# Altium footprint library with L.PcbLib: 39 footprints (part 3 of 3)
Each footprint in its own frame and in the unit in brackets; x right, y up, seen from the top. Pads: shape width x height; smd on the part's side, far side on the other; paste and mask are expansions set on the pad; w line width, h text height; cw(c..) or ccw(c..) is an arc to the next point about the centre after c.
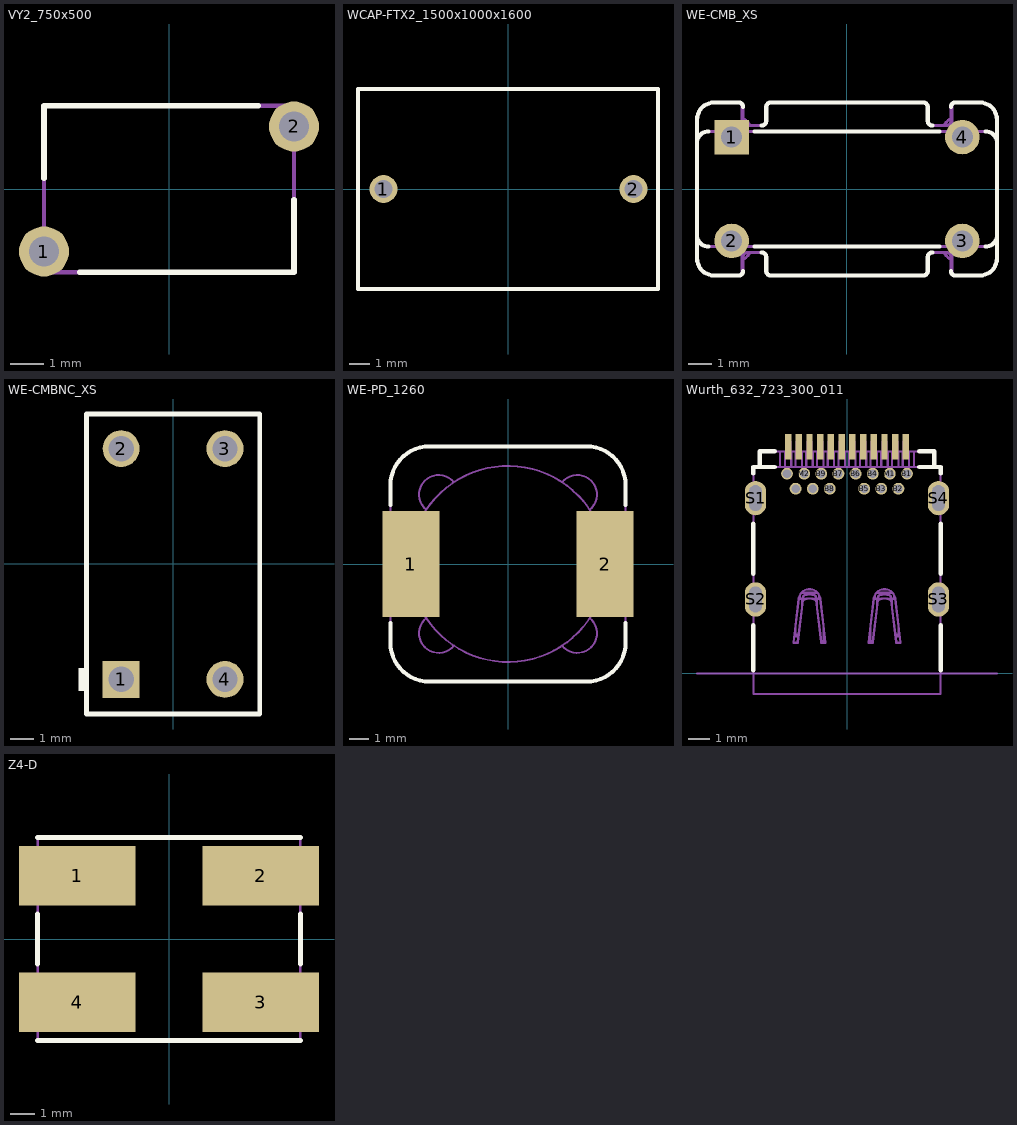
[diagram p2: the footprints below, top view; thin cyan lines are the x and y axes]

## VY2_750x500 [mm] "Vishay"
height 10.5
pads (2):
  round 1.5 hole 0.889: 1(-3.75,-1.875) 2(3.75,1.875)
Top Overlay:
  lines w0.17: -3.75,0.325 -3.75,2.5 2.675,2.5 ; -2.675,-2.5 3.75,-2.5 3.75,-0.325
Mechanical 5:
  lines w0.127: -3.75,-1.25 -3.75,1.25 ; 3.75,-1.25 3.75,1.25 ; -3.75,-2.5 -3.75,2.5 3.75,2.5 3.75,-2.5 -3.75,-2.5
3D body: height 5.5, standoff -1.5, extent -4.05,-2.174 -3.452,-1.576
3D body: height 5.5, standoff -1.5, extent 3.45,1.576 4.048,2.174
3D body: height 10.5, standoff 3, extent -3.75,-2.5 3.75,2.5

## WCAP-FTX2_1500x1000x1600 [mm] "TH, 2-Leads, Body 15x10mm, Pin Spacing 12.5mm"
height 16.5
pads (2):
  round 1.4 hole 0.9: 1(-6.25,0) 2(6.25,0)
Top Overlay:
  lines w0.2: -7.525,-5 7.475,-5 7.475,5 -7.525,5 -7.525,-5
Mechanical 5:
  lines w0.1: -7.525,-5 -7.525,5 7.475,5 7.475,-5 -7.525,-5
3D body "890324024005.stp": height 16, standoff -20, extent -7.5,-5 7.5,5

## WE-CMB_XS [mm] "WE-CMB Series Size XS"
height 18
pads (4):
  rect 1.5x1.5 hole 0.9: 1(-5,2.25)
  round 1.5 hole 0.9: 2(-5,-2.25) 3(5,-2.25) 4(5,2.25)
Top Overlay:
  lines w0.178: -6,-2.5 cw(c-6,-2) -6.5,-2 ; -6,2.5 ccw(c-6,2) -6.5,2 ; -4.5,-3.55 cw(c-4.7,-3.55) -4.543,-3.674 cw(c-4.7,-3.55) -4.7,-3.75 -5.75,-3.75 cw(c-5.75,-3) -6.5,-3 -6.5,-2 ; -4.5,3.55 ccw(c-4.7,3.55) -4.543,3.674 ccw(c-4.7,3.55) -4.7,3.75 -5.75,3.75 ccw(c-5.75,3) -6.5,3 -6.5,2 ; -4,-2.5 0,-2.5 4,-2.5 ; -4,2.5 0,2.5 4,2.5 ; -3.7,-2.75 cw(c-3.7,-2.95) -3.5,-2.95 -3.5,-3.55 ccw(c-3.3,-3.55) -3.3,-3.75 3.3,-3.75 ccw(c3.3,-3.55) 3.5,-3.55 3.5,-2.95 cw(c3.7,-2.95) 3.7,-2.75 ; -3.7,2.75 ccw(c-3.7,2.95) -3.5,2.95 -3.5,3.55 cw(c-3.3,3.55) -3.3,3.75 3.3,3.75 cw(c3.3,3.55) 3.5,3.55 3.5,2.95 ccw(c3.7,2.95) 3.7,2.75 ; 4.5,-3.55 ccw(c4.7,-3.55) 4.543,-3.674 ccw(c4.7,-3.55) 4.7,-3.75 5.75,-3.75 ccw(c5.75,-3) 6.5,-3 6.5,-2 ; 4.5,3.55 cw(c4.7,3.55) 4.543,3.674 cw(c4.7,3.55) 4.7,3.75 5.75,3.75 cw(c5.75,3) 6.5,3 6.5,2 ; 6,-2.5 ccw(c6,-2) 6.5,-2 ; 6,2.5 cw(c6,2) 6.5,2 ; -6.5,-2 -6.5,2 ; 6.5,-2 6.5,2
Mechanical 5:
  lines w0.127: -4.543,-2.5 -4.543,-3.674 ; -4.543,2.5 -4.543,3.674 ; -4.5,-3.058 ccw(c-5,-2.25) -4.192,-2.75 ; -4.5,3.058 cw(c-5,2.25) -4.192,2.75 ; 4.192,-2.75 ccw(c5,-2.25) 4.5,-3.058 ; 4.192,2.75 cw(c5,2.25) 4.5,3.058 ; 4.543,-2.5 4.543,-3.674 ; 4.543,2.5 4.543,3.674 ; -6.5,-2 ccw(c-6,-2) -6,-2.5 0,-2.5 6,-2.5 ccw(c6,-2) 6.5,-2 ; -6.5,-2 -6.5,2 ; -6.5,-2 -6.5,-3 ccw(c-5.75,-3) -5.75,-3.75 -4.7,-3.75 ccw(c-4.7,-3.55) -4.543,-3.674 ; -6.5,2 cw(c-6,2) -6,2.5 0,2.5 6,2.5 cw(c6,2) 6.5,2 ; -6.5,2 -6.5,3 cw(c-5.75,3) -5.75,3.75 -4.7,3.75 cw(c-4.7,3.55) -4.543,3.674 ; -4.543,-3.674 ccw(c-4.7,-3.55) -4.5,-3.55 -4.5,-2.95 cw(c-4.3,-2.95) -4.3,-2.75 -3.7,-2.75 cw(c-3.7,-2.95) -3.5,-2.95 -3.5,-3.55 ccw(c-3.3,-3.55) -3.3,-3.75 3.3,-3.75 ccw(c3.3,-3.55) 3.5,-3.55 3.5,-2.95 cw(c3.7,-2.95) 3.7,-2.75 4.3,-2.75 cw(c4.3,-2.95) 4.5,-2.95 4.5,-3.55 ccw(c4.7,-3.55) 4.543,-3.674 ; -4.543,3.674 cw(c-4.7,3.55) -4.5,3.55 -4.5,2.95 ccw(c-4.3,2.95) -4.3,2.75 -3.7,2.75 ccw(c-3.7,2.95) -3.5,2.95 -3.5,3.55 cw(c-3.3,3.55) -3.3,3.75 3.3,3.75 cw(c3.3,3.55) 3.5,3.55 3.5,2.95 ccw(c3.7,2.95) 3.7,2.75 4.3,2.75 ccw(c4.3,2.95) 4.5,2.95 4.5,3.55 cw(c4.7,3.55) 4.543,3.674 ; 4.543,-3.674 ccw(c4.7,-3.55) 4.7,-3.75 5.75,-3.75 ccw(c5.75,-3) 6.5,-3 6.5,-2 ; 4.543,3.674 cw(c4.7,3.55) 4.7,3.75 5.75,3.75 cw(c5.75,3) 6.5,3 6.5,2 ; 6.5,-2 6.5,2
3D body "WE-CMB_XS.stp": height 16.24, standoff -3.58, extent -6.5,-3.75 6.5,3.75

## WE-CMBNC_XS [mm] "TH, 4-Leads, Body 14x7.5mm"
height 16
pads (4):
  rect 1.6x1.6 hole 1.1: 1(-2.25,-5)
  round 1.6 hole 1.1: 2(-2.25,5) 3(2.25,5) 4(2.25,-5)
Top Overlay:
  rectangle: -4.1,-5.5 -3.75,-4.5
  lines w0.2: -3.75,-6.5 3.75,-6.5 3.75,6.5 -3.75,6.5 -3.75,-6.5
Mechanical 5:
  circle w0.1: c-2.25,-5 r0.5
  lines w0.1: -3.75,-6.5 -3.75,6.5 3.75,6.5 3.75,-6.5 -3.75,-6.5
3D body "7448011305.stp": height 14.6, standoff -2.5, extent -3.75,-6.5 3.75,6.5

## WE-PD_1260 [mm] "Wurth Elektronik recommended land pattern"
height 6
pads (2):
  rect 2.9x5.4 smd: 1(-4.95,0) 2(4.95,0)
Top Overlay:
  lines w0.2: -6,-3 -6,-4.003 ccw(c-4,-4.003) -4,-6.003 4,-6.003 ccw(c4,-4.003) 6,-4.003 6,-3 ; -6,3 -6,4.003 cw(c-4,4.003) -4,6.003 4,6.003 cw(c4,4.003) 6,4.003 6,3
Mechanical 5:
  circle w0.1: c0,0.003 r5
  lines w0.1: -4.168,-2.758 ccw(c-3.536,-3.533) -2.761,-4.165 ; -4.168,2.764 cw(c-3.536,3.538) -2.761,4.171 ; 2.761,-4.165 ccw(c3.536,-3.533) 4.168,-2.758 ; 2.761,4.171 cw(c3.536,3.538) 4.168,2.764 ; -6,-3.997 ccw(c-4,-3.997) -4,-5.997 4,-5.997 ccw(c4,-3.997) 6,-3.997 6,4.003 ccw(c4,4.003) 4,6.003 -4,6.003 ccw(c-4,4.003) -6,4.003 -6,-3.997
3D body "WE-PD_1260.stp": height 6.01, standoff 0.01, extent -6,-6 6,6

## Wurth_632_723_300_011 [mm] "Connector, Receptacle, USB Type C, R/A"
height 3.11
pads (30):
  rect 0.3x1.2 smd: A1(-2.75,10.58) A2(-2.25,10.58) A3(-1.75,10.58) A4(-1.25,10.58) A5(-0.75,10.58) A6(-0.25,10.58) A7(0.25,10.58) A8(0.75,10.58) A9(1.25,10.58) A10(1.75,10.58) A11(2.25,10.58) A12(2.75,10.58)
  round 0.55 hole 0.4: B1(2.8,9.32) B2(2.4,8.62) B3(1.6,8.62) B4(1.2,9.32) B5(0.8,8.62) B6(0.4,9.32) B7(-0.4,9.32) B8(-0.8,8.62) B9(-1.2,9.32) B10(-1.6,8.62) B11(-2.4,8.62) B12(-2.8,9.32) M1(2,9.32) M2(-2,9.32)
  rrect100% 1x1.6 hole 0.6 slot 1.2 at 90 deg: S1(-4.27,8.18) S2(-4.27,3.45) S3(4.27,3.45) S4(4.27,8.18)
Top Overlay:
  lines w0.2: -4.37,0.15 -4.37,2.25 ; -4.37,4.65 -4.37,6.98 ; -4.37,9.325 -4.37,9.631 -3.37,9.631 ; -4.07,9.631 -4.07,10.361 -3.375,10.361 ; 3.37,9.631 4.37,9.631 4.37,9.325 ; 3.375,10.361 4.07,10.361 4.07,9.631 ; 4.37,0.15 4.37,2.25 ; 4.37,4.65 4.37,6.98
Mechanical 1:
  lines w0.1: -7,0 7,0
Mechanical 5:
  drawing of 6386 lines, arcs and shapes, not listed
3D body "632723100011.stp": height 3.07, standoff -1.78, extent -4.37,-0.965 4.37,10.829

## Z4-D [mm] "SMD, 4-Leads, Body 8.1x10.5mm"
height 1.55
pads (4):
  rect 4.7x2.4 smd: 1(-3.7,2.55) 2(3.7,2.55) 3(3.7,-2.55) 4(-3.7,-2.55)
Top Overlay:
  lines w0.2: -5.3,-4.1 5.3,-4.1 ; -5.3,-1 -5.3,1 ; -5.3,4.1 5.3,4.1 ; 5.3,-1 5.3,1
Mechanical 5:
  lines w0.1: -5.3,-4.1 -5.3,4.1 5.3,4.1 5.3,-4.1 -5.3,-4.1
3D body: height 1.55, standoff 0, extent -5.3,-4.1 5.3,4.1
3D body: height 1.56, standoff 1.54, extent -3.996,2.001 -3,2.999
